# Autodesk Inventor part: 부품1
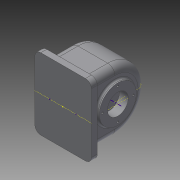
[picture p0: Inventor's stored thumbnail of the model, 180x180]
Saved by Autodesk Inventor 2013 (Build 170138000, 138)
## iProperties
Created: 2018-07
Part Number: 부품1
Material: 일반
Document SubType Name: Modeling
Designer: 05-01
Density: 1 g/cm^3
Author: 05-01
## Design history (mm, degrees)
sketch "스케치1"
  geometry: L1 (47.5, -60)-(-47.5, -60); L2 (-47.5, -60)-(-47.5, 60); L3 (-47.5, 60)-(47.5, 60); L4 (47.5, 60)-(47.5, -60); L5 (47.5, -60)-(-47.5, 60); L6 (-47.5, -60)-(47.5, 60); 1 further point
  constraints: 12 end point, 2 midpoint, 2 parallel, 1 horizontal, 1 perpendicular
  dimensions: "d0" = 120 distance of L3.end L1.start; "d2" = 95 distance of L2.end L3.end
extrude "돌출1" new body sketch "스케치1" distance "d3" = 10; taper "d4" = 0 deg
sketch "스케치2"
  geometry: L1 (37, -51)-(-37, -51); L2 (-37, -51)-(-37, 51); L3 (-37, 51)-(37, 51); L4 (37, 51)-(37, -51); L5 (37, -51)-(-37, 51); L6 (-37, -51)-(37, 51); 1 further point
  constraints: 12 end point, 2 midpoint, 2 parallel, 1 horizontal, 1 perpendicular
  dimensions: "d5" = 74 distance of L2.end L3.end; "d7" = 102 distance of L3.end L1.start
extrude "돌출2" join sketch "스케치2" distance "d8" = 40; taper "d9" = 0 deg
sketch "스케치3"
  geometry: L1 (-37, -51)-(37, -51) reference; L2 (37, -51)-(37, 51) reference; L3 (-37, 51)-(-37, -51) reference; L4 (-37, 0)-(37, 0); 1 further point
  constraints: 2 end point, 2 midpoint
revolve "회전1" sketch "스케치3" stored, may be unused: angle "d10" = 180 deg
sketch "스케치4"
  geometry: C1 r 31 at (51, 40); A1 r 51 centre (51, 40) between (102, 40) and (0, 40) reference; 1 further point
  constraints: 1 centre point, 1 coincident
  dimensions: "d11" = 62 diameter of C1
extrude "돌출3" join sketch "스케치4" distance "d13" = 5; taper "d14" = 0 deg
hole "구멍1" diameter "d17" = 35; stored, may be unused: countersink angle "d21" = 90 deg, drill point angle "d23" = 0 deg; dims "d18" = 6, "d19" = 4, "d20" = 2, "d22" = 15, "d24" = 10, "d25" = 10
node "작업 평면1"
hole "구멍2" diameter "d28" = 42; stored, may be unused: countersink angle "d32" = 90 deg, drill point angle "d34" = 0 deg; dims "d26" = 10, "d27" = 10, "d29" = 6, "d30" = 4, "d31" = 2, "d33" = 15
node "작업 평면2"
sketch "스케치5"
  geometry: 1 further point
fillet "모깎기1" dims "d35" = 12, "d36" = 3
fillet "모깎기2" dims "d37" = 3
sketch "스케치6"
  geometry: L1 (62, 91)-(12, 91) reference; L2 (62, 82)-(12, 82); L3 (0, 40)-(0, 79) reference; L4 (74, 79)-(74, 40) reference; L5 (65, 79)-(65, 74); L6 (9, 79)-(9, 74); L7 (15, 71)-(15, 40); L8 (59, 71)-(59, 40); L9 (79, 57.5)-(79, 22.5) reference; L10 (-5, 19)-(-5, 61) reference; L11 (-10.5, -10)-(84.5, -10) reference; L12 (-10.5, 40)-(84.5, 40); L13 (62, 71)-(59, 71); L14 (15, 71)-(12, 71); A1 r 12 centre (12, 79) between (12, 91) and (0, 79) reference; A2 r 12 centre (62, 79) between (74, 79) and (62, 91) reference; A3 r 3 centre (62, 79) between (65, 79) and (62, 82); A4 r 3 centre (12, 79) between (12, 82) and (9, 79); A5 r 3 centre (12, 74) between (9, 74) and (12, 71); A6 r 3 centre (62, 74) between (62, 71) and (65, 74); 4 further points
  constraints: 16 end point, 12 tangent, 8 point on circle, 4 centre point, 4 parallel, 2 perpendicular, 2 point on line, 1 equal radius, 1 symmetric about line
  dimensions: "d38" = 9 distance between parallel lines of L2 L1; "d39" = 9 radial gap between concentric circles of A4 A1; "d40" = 9 radial gap between concentric circles of A3 A2; "d41" = 56 distance of L5.start L6.start; "d43" = 3 radius of A5; "d45" = 50 distance between parallel lines of L12 L11; "d46" = 20 distance between parallel lines of L13 L1; "d47" = 5.5 distance from line of L12.end L9; "d48" = 17 distance from line of L2.start L9; "d49" = 17 distance from line of A3.end L9; "d50" = 20 distance from line of point (59, -10) L9; "d51" = 101 distance from line of point (59, -10) L1; "d53" = 67 distance from line of L2.end L9; "d54" = 67 distance from line of A4.start L9; "d55" = 89.5 distance from line of L12.start L9; "d56" = 64 distance from line of point (15, -10) L9; "d57" = 101 distance from line of point (15, -10) L1
fillet "모깎기3" dims "d58" = 10
sketch "스케치7"
  geometry: C1 r 17.5 at (0, 0) reference; 5 further points
  constraints: 5 other
  dimensions: "d59" = 26 distance of point (0, 26) C1.centre; "d62" = 360 deg dimension on C1.centre point (0, 26) (derived)
hole "구멍3" sketch "스케치7" at (0, 26) diameter "d64" = 3.242; stored, may be unused: countersink angle "d68" = 90 deg, drill point angle "d70" = 118 deg; dims "d65" = 6, "d66" = 4, "d67" = 2, "d69" = 9
node "솔리드1"
mirror "대칭1"
pattern_circular "원형 패턴1" dims angle "d72" = 360 deg
mirror "대칭2"
node "작업 평면3"
other parameters: "d42" = 11
